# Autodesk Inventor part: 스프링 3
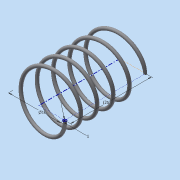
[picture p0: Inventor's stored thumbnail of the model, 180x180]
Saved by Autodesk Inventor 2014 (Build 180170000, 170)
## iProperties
Created: 2015-06
Part Number: 스프링 3
Material: 강철, 연강
Document SubType Name: Modeling
Designer: Administrator
Density: 7.86 g/cm^3
Appearance: 강철
Mass: 1.5292 g
Surface Area: 7.8715 cm^2
Volume: 0.194555 cm^3
Author: Administrator
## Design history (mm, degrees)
sketch "스케치1"
  geometry: L1 (0, 0)-(8, 0); L2 (8, 0)-(8, 14.5); L3 (8, 14.5)-(0, 14.5); L4 (0, 14.5)-(0, 0); C1 r 0.5 at (8, 0)
  constraints: 8 end point, 2 parallel, 1 centre point, 1 coincident, 1 horizontal, 1 perpendicular
  dimensions: "d0" = 1 diameter of C1; "d1" = 16 diameter of L2 L4; "d2" = 14.5 distance of L1.end L2.end (derived)
feature "코일1" pitch "d3" = 10; turns "d5" = 5; dims "d4" = 14.5 (= d2), "d6" = 0, angle "d7" = 90 deg, angle "d8" = 90 deg, "d9" = 0, "d10" = 0
sketch "스케치2"
  geometry: L1 (-8.5, 0)-(-7.5, 0) reference; L2 (-8.5, 0)-(-7.5, 0) reference; 1 further point
  constraints: 2 horizontal alignment
extrude "돌출1" cut sketch "스케치2" stored distance "d11" = 10; taper "d12" = 0 deg
node "작업 평면1"
sketch "스케치3"
  geometry: L1 (8.5, 0)-(7.5, 0) reference; 1 further point
  constraints: 1 horizontal alignment
extrude "돌출2" cut sketch "스케치3" stored distance "d14" = 10; taper "d15" = 0 deg
node "솔리드1"
node "절단 모서리 투영1"
node "절단 모서리 투영2"
node "절단 모서리 투영3"
other parameters: "d13" = -14.5 (= -d2)
